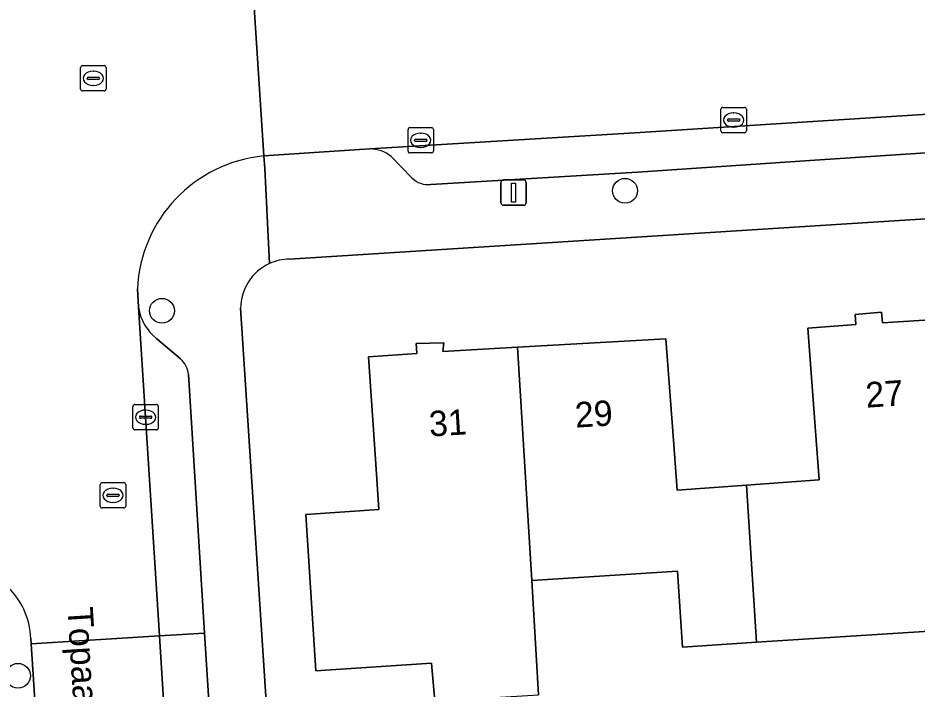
# Model space of a CAD drawing. Extents: x 159626 to 160723, y 388173 to 389416.
# Drawn here: x 160357.7 to 160393.1, y 388464.98 to 388491.42 of the extents above; entities that cross this region are included whole.
import ezdxf

# ---------------------------------------------------------------- set-up
doc = ezdxf.new("R2010")
doc.units = 0
for name, color, linetype in [('IMGEO_Boom', 7, 'Continuous'), ('IMGEO_Erf', 7, 'Continuous'), ('IMGEO_Kolk', 7, 'Continuous'), ('IMGEO_Lichtmast', 7, 'Continuous'), ('IMGEO_Openbare_ruimte_label', 7, 'Continuous'), ('IMGEO_Pand', 7, 'Continuous'), ('IMGEO_Pand_nummerreeks', 7, 'Continuous'), ('IMGEO_Parkeervlak_open', 7, 'Continuous'), ('IMGEO_Rijbaan_lokaal_open', 7, 'Continuous'), ('IMGEO_Rioolput', 7, 'Continuous'), ('IMGEO_Voetpad_open', 7, 'Continuous')]:
    doc.layers.add(name, color=color, linetype=linetype)

msp = doc.modelspace()

# ---------------------------------------------------------------- linework, layer by layer
at = {"layer": 'IMGEO_Boom'}
for centre in [(160381.602, 388484.612), (160363.369, 388479.883), (160357.7, 388465.499)]:
    msp.add_circle(centre, 0.489, dxfattribs=at)
at = {"layer": 'IMGEO_Erf'}
for points in [[(160431.43, 388478.134), (160430.92, 388485.882), (160368.394, 388481.92)], [(160366.464, 388479.982), (160370.129, 388423.835)], [(160374.119, 388464.501), (160373.977, 388465.992), (160369.43, 388465.699), (160369.038, 388471.855), (160371.908, 388472.052), (160371.772, 388474.034), (160371.495, 388478.064), (160373.4, 388478.195), (160373.372, 388478.596), (160374.461, 388478.617), (160374.433, 388478.283), (160377.366, 388478.449), (160383.212, 388478.781), (160383.511, 388474.787), (160383.659, 388472.81), (160386.378, 388473.014), (160389.242, 388473.228), (160389.099, 388475.145), (160388.796, 388479.2), (160390.687, 388479.342), (160390.658, 388479.741), (160391.702, 388479.834), (160391.74, 388479.41), (160394.627, 388479.593)], [(160395.243, 388467.368), (160389.666, 388467.007), (160386.781, 388466.82), (160383.858, 388466.631), (160383.665, 388469.625), (160377.931, 388469.253), (160378.196, 388464.746)]]:
    msp.add_lwpolyline(points, dxfattribs=at)
for centre, radius, start, end in [((160368.413, 388479.971), 1.949, 114.5933, 179.6637), ((160368.416, 388479.96), 1.96, 90.6492, 114.5463)]:
    msp.add_arc(centre, radius, start, end, dxfattribs=at)
at = {"layer": 'IMGEO_Kolk'}
for p, q in [((160385.377, 388486.973), (160385.377, 388487.825)), ((160385.452, 388487.899), (160386.304, 388487.899)), ((160385.865, 388487.679), (160385.89, 388487.679)), ((160386.378, 388487.825), (160386.378, 388486.973)), ((160385.636, 388487.393), (160385.636, 388487.405)), ((160386.074, 388487.356), (160385.676, 388487.356)), ((160385.679, 388487.442), (160386.077, 388487.442)), ((160386.12, 388487.405), (160386.12, 388487.393)), ((160373.057, 388486.178), (160373.057, 388487.03)), ((160373.132, 388487.104), (160373.984, 388487.104)), ((160374.058, 388487.03), (160374.058, 388486.178)), ((160385.888, 388487.119), (160385.863, 388487.119)), ((160373.316, 388486.598), (160373.316, 388486.61)), ((160373.359, 388486.647), (160373.757, 388486.647)), ((160373.545, 388486.884), (160373.57, 388486.884)), ((160373.8, 388486.61), (160373.8, 388486.598)), ((160386.304, 388486.899), (160385.452, 388486.899)), ((160373.754, 388486.561), (160373.356, 388486.561)), ((160373.568, 388486.324), (160373.543, 388486.324)), ((160373.984, 388486.104), (160373.132, 388486.104)), ((160362.225, 388475.265), (160362.225, 388476.117)), ((160362.3, 388476.191), (160363.152, 388476.191)), ((160363.226, 388476.117), (160363.226, 388475.265)), ((160362.484, 388475.685), (160362.484, 388475.697)), ((160362.922, 388475.648), (160362.524, 388475.648)), ((160362.527, 388475.734), (160362.925, 388475.734)), ((160362.713, 388475.971), (160362.738, 388475.971)), ((160362.968, 388475.697), (160362.968, 388475.685)), ((160362.736, 388475.411), (160362.711, 388475.411)), ((160363.152, 388475.191), (160362.3, 388475.191))]:
    msp.add_line(p, q, dxfattribs=at)
for points in [[(160385.377, 388486.973), (160385.377, 388487.825)], [(160385.452, 388487.899), (160386.304, 388487.899)], [(160386.378, 388487.825), (160386.378, 388486.973)], [(160373.057, 388486.178), (160373.057, 388487.03)], [(160373.132, 388487.104), (160373.984, 388487.104)], [(160374.058, 388487.03), (160374.058, 388486.178)], [(160386.304, 388486.899), (160385.452, 388486.899)], [(160373.984, 388486.104), (160373.132, 388486.104)], [(160362.225, 388475.265), (160362.225, 388476.117)], [(160362.3, 388476.191), (160363.152, 388476.191)], [(160363.226, 388476.117), (160363.226, 388475.265)], [(160363.152, 388475.191), (160362.3, 388475.191)]]:
    msp.add_lwpolyline(points, dxfattribs=at)
for centre, radius, start, end in [((160385.454, 388487.823), 0.0765, 91.552, 178.448), ((160385.454, 388487.823), 0.0765, 91.552, 178.448), ((160386.302, 388487.823), 0.0765, 1.552, 88.448), ((160386.302, 388487.823), 0.0765, 1.552, 88.448), ((160385.676, 388487.402), 0.0403, 85.8775, 175.7526), ((160385.673, 388487.392), 0.0366, 178.938, 274.7102), ((160386.077, 388487.399), 0.043, 264.8664, 352.4533), ((160386.081, 388487.404), 0.0386, 1.7309, 96.639), ((160373.134, 388487.028), 0.0765, 91.552, 178.448), ((160373.134, 388487.028), 0.0765, 91.552, 178.448), ((160373.982, 388487.028), 0.0765, 1.552, 88.448), ((160373.982, 388487.028), 0.0765, 1.552, 88.448), ((160385.454, 388486.975), 0.0765, 181.552, 268.448), ((160385.454, 388486.975), 0.0765, 181.552, 268.448), ((160386.302, 388486.975), 0.0765, 271.552, 358.448), ((160386.302, 388486.975), 0.0765, 271.552, 358.448), ((160373.356, 388486.607), 0.0403, 85.8775, 175.7526), ((160373.761, 388486.609), 0.0386, 1.7309, 96.639), ((160373.353, 388486.597), 0.0366, 178.938, 274.7102), ((160373.757, 388486.604), 0.043, 264.8664, 352.4533), ((160373.134, 388486.18), 0.0765, 181.552, 268.448), ((160373.134, 388486.18), 0.0765, 181.552, 268.448), ((160373.982, 388486.18), 0.0765, 271.552, 358.448), ((160373.982, 388486.18), 0.0765, 271.552, 358.448), ((160362.302, 388476.115), 0.0765, 91.552, 178.448), ((160362.302, 388476.115), 0.0765, 91.552, 178.448), ((160363.15, 388476.115), 0.0765, 1.552, 88.448), ((160363.15, 388476.115), 0.0765, 1.552, 88.448), ((160362.524, 388475.694), 0.0403, 85.8775, 175.7526), ((160362.521, 388475.684), 0.0366, 178.938, 274.7102), ((160362.925, 388475.691), 0.043, 264.8664, 352.4533), ((160362.929, 388475.696), 0.0386, 1.7309, 96.639), ((160362.302, 388475.267), 0.0765, 181.552, 268.448), ((160362.302, 388475.267), 0.0765, 181.552, 268.448), ((160363.15, 388475.267), 0.0765, 271.552, 358.448), ((160363.15, 388475.267), 0.0765, 271.552, 358.448)]:
    msp.add_arc(centre, radius, start, end, dxfattribs=at)
for centre, major_axis, ratio, start_param, end_param in [((160385.864, 388487.399), (-0.387, 0.002), 0.722429, 4.712389, 7.853982), ((160385.889, 388487.399), (-0.39, 0.002), 0.717154, 1.570796, 4.712389), ((160373.544, 388486.604), (-0.387, 0.002), 0.722429, 4.712389, 7.853982), ((160373.569, 388486.604), (-0.39, 0.002), 0.717154, 1.570796, 4.712389), ((160362.712, 388475.691), (-0.387, 0.002), 0.722429, 4.712389, 7.853982), ((160362.737, 388475.691), (-0.39, 0.002), 0.717154, 1.570796, 4.712389)]:
    msp.add_ellipse(centre, major_axis=major_axis, ratio=ratio, start_param=start_param, end_param=end_param, dxfattribs=at)
at = {"layer": 'IMGEO_Lichtmast'}
for p, q in [((160376.717, 388484.14), (160376.717, 388484.94)), ((160376.717, 388484.94), (160376.717, 388484.14)), ((160376.817, 388485.04), (160377.607, 388485.04)), ((160377.607, 388485.04), (160376.817, 388485.04)), ((160377.707, 388484.94), (160377.707, 388484.14)), ((160377.707, 388484.14), (160377.707, 388484.94)), ((160377.607, 388484.04), (160376.817, 388484.04)), ((160376.817, 388484.04), (160377.607, 388484.04))]:
    msp.add_line(p, q, dxfattribs=at)
msp.add_lwpolyline([(160377.137, 388484.915), (160377.287, 388484.915), (160377.287, 388484.165), (160377.137, 388484.165), (160377.137, 388484.915)], dxfattribs=at)
for centre, start, end in [((160376.817, 388484.94), 90, 180), ((160376.817, 388484.94), 90, 180), ((160377.607, 388484.94), 0, 90), ((160377.607, 388484.94), 360, 90), ((160376.817, 388484.14), 180, 270), ((160376.817, 388484.14), 180, 270), ((160377.607, 388484.14), 270, 0), ((160377.607, 388484.14), 270, 0)]:
    msp.add_arc(centre, 0.1, start, end, dxfattribs=at)
at = {"layer": 'IMGEO_Pand'}
for points in [[(160394.627, 388479.593), (160391.74, 388479.41), (160391.702, 388479.834), (160390.658, 388479.741), (160390.687, 388479.342), (160388.796, 388479.2), (160389.099, 388475.145), (160389.242, 388473.228), (160386.378, 388473.014), (160386.781, 388466.82), (160389.666, 388467.007), (160395.243, 388467.368), (160395.053, 388470.362), (160395.211, 388470.372)], [(160377.366, 388478.449), (160374.433, 388478.283), (160374.461, 388478.617), (160373.372, 388478.596), (160373.4, 388478.195), (160371.495, 388478.064), (160371.772, 388474.034), (160371.908, 388472.052), (160369.038, 388471.855), (160369.43, 388465.699), (160373.977, 388465.992), (160374.119, 388464.501), (160378.196, 388464.746), (160377.931, 388469.253)], [(160386.378, 388473.014), (160383.659, 388472.81), (160383.511, 388474.787), (160383.212, 388478.781), (160377.366, 388478.449), (160377.931, 388469.253), (160383.665, 388469.625), (160383.858, 388466.631), (160386.781, 388466.82)]]:
    msp.add_lwpolyline(points, close=True, dxfattribs=at)
at = {"layer": 'IMGEO_Parkeervlak_open'}
for points in [[(160430.419, 388490.022), (160430.026, 388489.997), (160428.063, 388489.866), (160422.859, 388489.52), (160416.087, 388489.084), (160406.093, 388488.441), (160399.309, 388488.005), (160388.781, 388487.328), (160381.99, 388486.891), (160371.556, 388486.262)], [(160373.952, 388484.861), (160382.089, 388485.351), (160388.881, 388485.8), (160399.403, 388486.496)], [(160372.394, 388485.966), (160373.213, 388485.119)], [(160362.443, 388480.027), (160362.721, 388475.691), (160363.266, 388467.074), (160365.049, 388467.186), (160364.415, 388477.386)], [(160364.105, 388477.984), (160363.163, 388478.782)]]:
    msp.add_lwpolyline(points, dxfattribs=at)
msp.add_lwpolyline([(160365.049, 388467.186), (160363.266, 388467.074), (160363.877, 388457.381), (160364.342, 388450.32), (160366.133, 388450.431), (160365.661, 388457.518)], close=True, dxfattribs=at)
for centre, radius, start, end in [((160371.557, 388484.931), 1.331, 51.0392, 90.0522), ((160373.855, 388485.771), 0.915, 225.4272, 276.0826), ((160364.341, 388480.294), 1.916, 188.0014, 232.0813), ((160363.459, 388477.27), 0.963, 6.9262, 47.8778)]:
    msp.add_arc(centre, radius, start, end, dxfattribs=at)
at = {"layer": 'IMGEO_Rijbaan_lokaal_open'}
msp.add_lwpolyline([(160427.705, 388495.851), (160424.131, 388495.627), (160420.362, 388495.391), (160408.897, 388494.672), (160402.116, 388494.248), (160366.987, 388492.046), (160367.38, 388485.986), (160371.152, 388486.237), (160371.556, 388486.262), (160381.99, 388486.891), (160388.781, 388487.328), (160399.309, 388488.005), (160406.093, 388488.441), (160416.087, 388489.084), (160422.859, 388489.52), (160428.063, 388489.866)], close=True, dxfattribs=at)
for points in [[(160367.38, 388485.986), (160366.987, 388492.046), (160365.977, 388491.983)], [(160358.205, 388466.963), (160358.219, 388466.756), (160363.266, 388467.074), (160362.721, 388475.691), (160362.443, 388480.027), (160362.401, 388480.744)], [(160364.342, 388450.32), (160363.877, 388457.381), (160363.266, 388467.074), (160358.219, 388466.756), (160358.43, 388463.522), (160360.883, 388425.982)]]:
    msp.add_lwpolyline(points, dxfattribs=at)
for centre, radius, start, end in [((160367.911, 388480.496), 5.516, 95.5281, 177.4198), ((160355.209, 388466.856), 2.998, 2.0463, 93.7932)]:
    msp.add_arc(centre, radius, start, end, dxfattribs=at)
at = {"layer": 'IMGEO_Rioolput'}
for p, q in [((160360.167, 388488.62), (160360.167, 388489.472)), ((160360.242, 388489.546), (160361.094, 388489.546)), ((160361.168, 388489.472), (160361.168, 388488.62)), ((160360.469, 388489.089), (160360.867, 388489.089)), ((160360.655, 388489.326), (160360.68, 388489.326)), ((160360.426, 388489.04), (160360.426, 388489.052)), ((160360.864, 388489.003), (160360.466, 388489.003)), ((160360.678, 388488.766), (160360.653, 388488.766)), ((160360.91, 388489.052), (160360.91, 388489.04)), ((160361.094, 388488.546), (160360.242, 388488.546)), ((160360.942, 388472.186), (160360.942, 388473.038)), ((160361.017, 388473.112), (160361.869, 388473.112)), ((160361.43, 388472.892), (160361.455, 388472.892)), ((160361.943, 388473.038), (160361.943, 388472.186)), ((160361.201, 388472.606), (160361.201, 388472.618)), ((160361.639, 388472.569), (160361.241, 388472.569)), ((160361.244, 388472.655), (160361.642, 388472.655)), ((160361.685, 388472.618), (160361.685, 388472.606)), ((160361.869, 388472.112), (160361.017, 388472.112)), ((160361.453, 388472.332), (160361.428, 388472.332))]:
    msp.add_line(p, q, dxfattribs=at)
for points in [[(160360.167, 388488.62), (160360.167, 388489.472)], [(160360.242, 388489.546), (160361.094, 388489.546)], [(160361.168, 388489.472), (160361.168, 388488.62)], [(160361.094, 388488.546), (160360.242, 388488.546)], [(160360.942, 388472.186), (160360.942, 388473.038)], [(160361.017, 388473.112), (160361.869, 388473.112)], [(160361.943, 388473.038), (160361.943, 388472.186)], [(160361.869, 388472.112), (160361.017, 388472.112)]]:
    msp.add_lwpolyline(points, dxfattribs=at)
for centre, radius, start, end in [((160360.244, 388489.47), 0.0765, 91.552, 178.448), ((160360.244, 388489.47), 0.0765, 91.552, 178.448), ((160361.092, 388489.47), 0.0765, 1.552, 88.448), ((160361.092, 388489.47), 0.0765, 1.552, 88.448), ((160360.466, 388489.049), 0.0403, 85.8775, 175.7526), ((160360.871, 388489.051), 0.0386, 1.7309, 96.639), ((160360.463, 388489.039), 0.0366, 178.938, 274.7102), ((160360.867, 388489.046), 0.043, 264.8664, 352.4533), ((160360.244, 388488.622), 0.0765, 181.552, 268.448), ((160360.244, 388488.622), 0.0765, 181.552, 268.448), ((160361.092, 388488.622), 0.0765, 271.552, 358.448), ((160361.092, 388488.622), 0.0765, 271.552, 358.448), ((160361.019, 388473.036), 0.0765, 91.552, 178.448), ((160361.019, 388473.036), 0.0765, 91.552, 178.448), ((160361.867, 388473.036), 0.0765, 1.552, 88.448), ((160361.867, 388473.036), 0.0765, 1.552, 88.448), ((160361.241, 388472.615), 0.0403, 85.8775, 175.7526), ((160361.238, 388472.605), 0.0366, 178.938, 274.7102), ((160361.642, 388472.612), 0.043, 264.8664, 352.4533), ((160361.646, 388472.617), 0.0386, 1.7309, 96.639), ((160361.019, 388472.188), 0.0765, 181.552, 268.448), ((160361.019, 388472.188), 0.0765, 181.552, 268.448), ((160361.867, 388472.188), 0.0765, 271.552, 358.448), ((160361.867, 388472.188), 0.0765, 271.552, 358.448)]:
    msp.add_arc(centre, radius, start, end, dxfattribs=at)
for centre, major_axis, ratio, start_param, end_param in [((160360.654, 388489.046), (-0.387, 0.002), 0.722429, 4.712389, 7.853982), ((160360.679, 388489.046), (-0.39, 0.002), 0.717154, 1.570796, 4.712389), ((160361.429, 388472.612), (-0.387, 0.002), 0.722429, 4.712389, 7.853982), ((160361.454, 388472.612), (-0.39, 0.002), 0.717154, 1.570796, 4.712389)]:
    msp.add_ellipse(centre, major_axis=major_axis, ratio=ratio, start_param=start_param, end_param=end_param, dxfattribs=at)
at = {"layer": 'IMGEO_Voetpad_open'}
for points in [[(160368.394, 388481.92), (160430.92, 388485.882), (160433.934, 388486.077), (160498.648, 388490.246)], [(160429.203, 388489.351), (160428.559, 388488.573), (160428.377, 388488.44), (160428.166, 388488.337), (160428.052, 388488.313), (160427.943, 388488.297), (160422.958, 388487.974), (160416.185, 388487.557), (160406.187, 388486.925), (160399.403, 388486.496), (160388.881, 388485.8), (160382.089, 388485.351), (160373.952, 388484.861)], [(160371.556, 388486.262), (160371.152, 388486.237), (160367.38, 388485.986), (160367.414, 388485.488), (160367.602, 388481.743)], [(160367.602, 388481.743), (160367.414, 388485.488), (160367.38, 388485.986)], [(160373.213, 388485.119), (160372.394, 388485.966)], [(160362.401, 388480.744), (160362.443, 388480.027)], [(160365.565, 388421.461), (160368.305, 388420.423), (160370.196, 388419.988), (160370.129, 388423.835), (160366.464, 388479.982)], [(160363.163, 388478.782), (160364.105, 388477.984)], [(160364.415, 388477.386), (160365.049, 388467.186), (160365.661, 388457.518), (160366.133, 388450.431), (160366.632, 388450.462), (160366.868, 388446.706), (160366.377, 388446.676), (160367.026, 388436.694), (160367.524, 388436.726), (160367.97, 388429.916), (160367.466, 388429.884), (160367.594, 388427.904)], [(160358.219, 388466.756), (160358.205, 388466.963)], [(160358.43, 388463.522), (160358.219, 388466.756)]]:
    msp.add_lwpolyline(points, dxfattribs=at)
for centre, radius, start, end in [((160371.557, 388484.931), 1.331, 51.0392, 90.0522), ((160367.911, 388480.496), 5.516, 95.5281, 177.4198), ((160373.855, 388485.771), 0.915, 225.4272, 276.0826), ((160368.413, 388479.971), 1.949, 114.5933, 179.6637), ((160368.416, 388479.96), 1.96, 90.6492, 114.5463), ((160364.341, 388480.294), 1.916, 188.0014, 232.0813), ((160363.459, 388477.27), 0.963, 6.9262, 47.8778), ((160355.209, 388466.856), 2.998, 2.0463, 93.7932)]:
    msp.add_arc(centre, radius, start, end, dxfattribs=at)

# ---------------------------------------------------------------- texts
at = {"layer": 'IMGEO_Openbare_ruimte_label'}
msp.add_text('Topaasring', height=1, rotation=273.5549, dxfattribs=at).set_placement((160359.646, 388468.179))
at = {"layer": 'IMGEO_Pand_nummerreeks'}
for s, rotation, p in [('27', 3.7414, (160391.099, 388476.064)), ('29', 3.5017, (160379.658, 388475.277)), ('31', 3.5008, (160373.912, 388474.926))]:
    msp.add_text(s, height=1, rotation=rotation, dxfattribs=at).set_placement(p)

doc.saveas('drawing.dxf')
